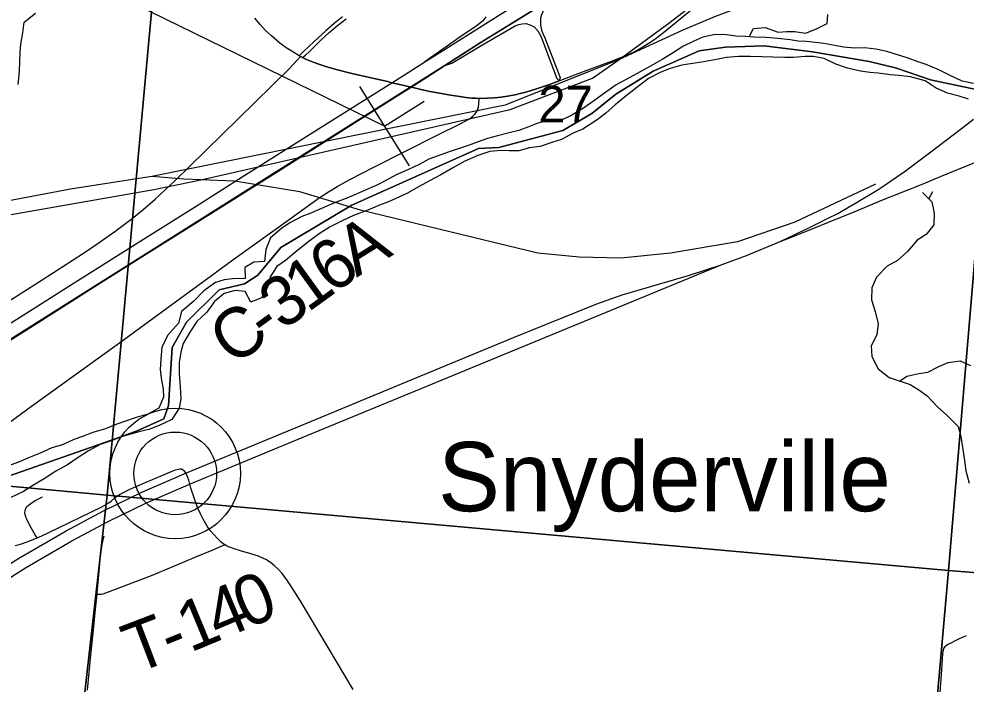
# Model space of a CAD drawing. Extents: x 0 to 1134, y 0 to 440.
# Drawn here: x 395.41 to 427.82, y 180.01 to 202.75 of the extents above; entities that cross this region are included whole.
import ezdxf

# ---------------------------------------------------------------- set-up
doc = ezdxf.new("R2010")
doc.units = 0
for name, color, linetype in [('Default', 7, 'Continuous'), ('GM_X_County_Road', 7, 'Continuous'), ('GM_X_County_Road_Text', 7, 'Continuous'), ('GM_X_Interchange_Ramps', 7, 'Continuous'), ('GM_X_Major_River', 7, 'Continuous'), ('GM_X_Minor_River', 7, 'Continuous'), ('GM_X_Rail_Line', 7, 'Continuous'), ('GM_X_Section', 7, 'Continuous'), ('GM_X_Section_Text', 7, 'Continuous'), ('GM_X_State_Location', 7, 'Continuous'), ('GM_X_State_Route', 7, 'Continuous'), ('GM_X_Township', 7, 'Continuous'), ('GM_X_Township_Road', 7, 'Continuous'), ('GM_X_Township_Road_Text', 7, 'Continuous'), ('GM_X_Unincorporated', 7, 'Continuous'), ('GM_X_Unincorporated_Location', 7, 'Continuous'), ('GM_X_Unincorporated_Text', 7, 'Continuous'), ('SH_Data', 7, 'Continuous'), ('SN_P_Signs', 7, 'Continuous')]:
    doc.layers.add(name, color=color, linetype=linetype)

msp = doc.modelspace()

# ---------------------------------------------------------------- linework, layer by layer
at = {"layer": 'Default'}
for points in [[(428.641, 212.888), (424.922, 210.575), (421.466, 208.395), (417.329, 205.771), (415.897, 204.869), (413.681, 203.473), (412.971, 203.034), (411.196, 201.936), (409.987, 201.156), (408.499, 200.212), (406.885, 199.202), (404.296, 197.561), (401.444, 195.77), (398.739, 194.065), (395.808, 192.216), (393.095, 190.508), (390.63, 188.941), (388.78, 187.783), (386.071, 186.068), (383.39, 184.383), (380.76, 182.721), (378.447, 181.267)], [(375.525, 180.013), (379.132, 182.26), (383.333, 184.928), (384.752, 185.823), (388.22, 188.011), (393.821, 191.534), (395.556, 192.627), (397.21, 193.672), (399.89, 195.36), (401.467, 196.354), (403.042, 197.35), (404.464, 198.24), (407.223, 199.98), (408.168, 200.573), (408.723, 200.921), (409.296, 201.282), (409.905, 201.666), (410.773, 202.212), (414.266, 204.419), (415.098, 204.944)], [(370.709, 176.423), (408.499, 200.212), (408.832, 200.421), (409.33, 200.733), (409.987, 201.156), (370.709, 176.423)]]:
    msp.add_lwpolyline(points, dxfattribs=at)
at = {"layer": 'GM_X_County_Road'}
msp.add_line((405.044, 201.463), (405.113, 201.431), dxfattribs=at)
for points in [[(413.898, 200.641), (414.34, 200.804), (414.817, 200.984), (415.689, 201.31), (416.207, 201.515), (416.457, 201.633), (416.701, 201.764), (416.938, 201.908), (417.168, 202.065), (417.462, 202.292), (418.472, 203.113)], [(394.394, 192.689), (396.204, 193.835), (397.614, 194.743), (398.155, 195.107), (398.686, 195.485), (399.282, 195.932), (399.645, 196.222), (400.064, 196.59), (400.749, 197.222), (401.247, 197.708), (403.477, 199.898), (404.674, 201.073), (405.044, 201.463)], [(405.113, 201.431), (405.246, 201.37), (405.472, 201.275), (405.702, 201.19), (405.948, 201.111), (406.261, 201.022), (406.798, 200.885), (408.018, 200.608), (408.168, 200.573), (408.493, 200.496), (408.832, 200.421), (409.033, 200.376), (409.12, 200.356)], [(409.12, 200.356), (409.471, 200.276), (409.868, 200.197), (410.178, 200.145), (410.493, 200.097), (410.702, 200.069), (410.91, 200.047), (411.034, 200.038), (411.161, 200.034)], [(411.161, 200.034), (411.426, 200.041), (411.678, 200.057), (411.914, 200.079), (412.122, 200.108), (412.386, 200.157), (412.561, 200.198), (412.75, 200.248), (413.121, 200.361), (413.593, 200.526), (413.898, 200.641)], [(393.607, 187.875), (395.714, 189.417), (398.888, 191.709), (400.472, 192.86), (401.828, 193.849), (402.731, 194.51), (404.697, 195.927), (405.685, 196.631), (405.996, 196.838), (406.316, 197.032), (406.726, 197.257), (407.556, 197.681), (409.72, 198.774), (410.555, 199.19), (410.798, 199.324), (410.874, 199.375), (410.945, 199.431), (411.009, 199.493), (411.065, 199.562), (411.105, 199.638), (411.135, 199.738), (411.15, 199.861), (411.161, 200.034)]]:
    msp.add_lwpolyline(points, dxfattribs=at)
at = {"layer": 'GM_X_Interchange_Ramps'}
for points in [[(406.484, 202.821), (406.189, 202.594), (405.905, 202.351), (405.494, 201.972), (405.161, 201.647), (405, 201.489)], [(405.113, 201.431), (405.21, 201.518), (405.349, 201.643), (405.747, 202.037), (406.024, 202.288), (406.31, 202.528), (406.608, 202.752)], [(411.381, 202.827), (411.33, 202.749), (411.269, 202.679), (411.2, 202.616), (411.052, 202.502), (410.5, 202.13), (409.296, 201.282)]]:
    msp.add_lwpolyline(points, dxfattribs=at)
at = {"layer": 'GM_X_Major_River'}
for points in [[(428.071, 200.539), (427.685, 200.628), (427.279, 200.819), (426.884, 201.01), (426.454, 201.191), (426.149, 201.3), (425.843, 201.41), (425.469, 201.52), (425.107, 201.642), (424.732, 201.719), (424.345, 201.762), (424.014, 201.758), (423.627, 201.789), (423.332, 201.841), (422.957, 201.918), (422.365, 201.976), (422.08, 201.994), (421.796, 202.034), (421.375, 202.089), (420.976, 202.121), (420.554, 202.13), (420.258, 202.148), (419.939, 202.166), (419.62, 202.208), (419.233, 202.216), (418.809, 202.134), (418.509, 201.992), (418.128, 201.807), (417.735, 201.564), (417.422, 201.366), (417.098, 201.179), (416.671, 200.949), (416.313, 200.751), (415.851, 200.499), (415.445, 200.211), (415.12, 199.979), (414.726, 199.702), (414.333, 199.46), (413.975, 199.285), (413.576, 199.305), (413.163, 199.189), (412.818, 199.048), (412.519, 198.94), (412.14, 198.846), (411.784, 198.751), (411.44, 198.667), (411.118, 198.549), (410.819, 198.441), (410.508, 198.334), (410.094, 198.195), (409.749, 198.066), (409.439, 197.958), (409.127, 197.783), (408.735, 197.609), (408.32, 197.424), (407.962, 197.226), (407.65, 197.073), (407.235, 196.889), (406.924, 196.747), (406.625, 196.628), (406.21, 196.466), (405.761, 196.27), (405.392, 196.107), (405.093, 196), (404.701, 195.792), (404.4, 195.593), (404.016, 195.271), (403.858, 194.863), (403.815, 194.453), (403.449, 194.439), (403.137, 194.252), (403.151, 193.875), (402.718, 193.861), (402.432, 193.834), (402.133, 193.737), (401.738, 193.449), (401.388, 193.103), (400.97, 192.747), (400.869, 192.35), (400.495, 191.925), (400.292, 191.519), (400.26, 191.131), (400.24, 190.755), (400.289, 190.401), (400.34, 190.103), (400.356, 189.817), (400.188, 189.444), (399.818, 189.236), (399.416, 189.119)], [(427.899, 200.007), (427.582, 200.116), (427.185, 200.216), (426.801, 200.385), (426.419, 200.632), (425.92, 200.769), (425.522, 200.823), (425.226, 200.841), (424.816, 200.896), (424.532, 200.925), (424.202, 200.966), (423.759, 201.067), (423.363, 201.201), (422.968, 201.404), (422.604, 201.469), (422.319, 201.464), (421.919, 201.438), (421.622, 201.434), (421.212, 201.443), (420.836, 201.462), (420.437, 201.471), (420.037, 201.468), (419.626, 201.432), (419.282, 201.371), (418.778, 201.279), (418.389, 201.219), (418.091, 201.169), (417.689, 201.052), (417.378, 200.933), (416.951, 200.714), (416.556, 200.404), (416.127, 200.082), (415.813, 199.815), (415.487, 199.526), (415.197, 199.304), (414.71, 198.984), (414.376, 198.843), (413.972, 198.635), (413.673, 198.539), (413.248, 198.388), (412.881, 198.339), (412.514, 198.245), (412.183, 198.24), (411.898, 198.258), (411.521, 198.221), (411.107, 198.081), (410.646, 197.875), (410.277, 197.677), (409.849, 197.424), (409.456, 197.216), (409.109, 197.018), (408.682, 196.788), (408.059, 196.494), (407.749, 196.387), (407.346, 196.213), (406.851, 196.03), (406.493, 195.855), (406.055, 195.648), (405.685, 195.405), (405.29, 195.117), (404.883, 194.784), (404.523, 194.495), (404.233, 194.285), (404.008, 193.936), (403.921, 193.607), (403.707, 193.212), (403.339, 193.072), (403.153, 193.43), (402.811, 193.471), (402.433, 193.366), (402.095, 193.088), (401.836, 192.728), (401.498, 192.405), (401.25, 192.045), (401.025, 191.651), (400.95, 191.356), (400.885, 191.004), (400.888, 190.627), (400.923, 190.17), (400.948, 189.759), (400.895, 189.44)], [(400.895, 189.44), (400.635, 189.058), (400.209, 188.851), (399.852, 188.71), (399.554, 188.648), (399.267, 188.563), (398.945, 188.468), (398.531, 188.317), (398.186, 188.199), (397.782, 187.98), (397.399, 187.726), (397.064, 187.505), (396.671, 187.285), (396.265, 187.021), (395.942, 186.834), (395.56, 186.591), (395.11, 186.373)], [(399.416, 189.119), (399.048, 189.002), (398.761, 188.894), (398.369, 188.731), (397.933, 188.604), (397.576, 188.475), (397.288, 188.367), (396.896, 188.182), (396.529, 188.087), (396.137, 187.902), (395.734, 187.74), (395.446, 187.62), (395.078, 187.48)]]:
    msp.add_lwpolyline(points, dxfattribs=at)
at = {"layer": 'GM_X_Minor_River'}
for points in [[(395.378, 200.505), (395.429, 200.96), (395.433, 201.313), (395.448, 201.609), (395.475, 201.893), (395.536, 202.28), (395.586, 202.644), (395.978, 202.947)], [(420.399, 202.14), (420.54, 202.428), (420.95, 202.457), (421.393, 202.304), (421.678, 202.323), (421.963, 202.32), (422.327, 202.27), (422.705, 202.414), (423.072, 202.592), (423.087, 202.91)], [(426.328, 196.812), (426.654, 196.501), (426.729, 196.113), (426.713, 195.714), (426.458, 195.375), (426.148, 195.186), (425.813, 194.802), (425.479, 194.487), (425.123, 194.298), (424.754, 193.926), (424.601, 193.552), (424.585, 193.142), (424.705, 192.742), (424.814, 192.331), (424.764, 191.944), (424.577, 191.57), (424.595, 191.206), (424.818, 190.782), (425.19, 190.493), (425.905, 190.245), (426.199, 190.071), (426.493, 189.862), (426.841, 189.482), (427.168, 189.205), (427.551, 188.813), (427.638, 188.47), (427.702, 188.105), (427.765, 187.649), (427.817, 187.295), (427.926, 186.872)], [(426.546, 196.604), (426.682, 196.854)], [(425.548, 190.369), (425.795, 190.531), (426.206, 190.629), (426.514, 190.671), (426.893, 190.871), (427.213, 191.004), (427.624, 191.056), (427.976, 190.904)]]:
    msp.add_lwpolyline(points, dxfattribs=at)
at = {"layer": 'GM_X_Rail_Line'}
for points in [[(415.945, 201.369), (417.65, 202.606), (424.392, 207.798), (441.828, 209.955)], [(440.214, 208.721), (437.468, 207.991), (422.252, 203.963), (419.273, 202.842), (418.129, 202.373), (415.945, 201.369)], [(415.945, 201.369), (412.045, 199.798), (399.953, 197.365)], [(401.626, 197.251), (412.216, 199.658), (415.032, 200.731), (415.945, 201.369)], [(421.456, 195.143), (422.465, 195.622), (423.06, 195.916), (423.428, 196.102), (423.8, 196.316), (424.014, 196.435), (424.834, 196.935), (425.705, 197.525), (426.617, 198.205), (427.659, 199.01), (428.072, 199.33)], [(421.456, 195.143), (421.702, 195.227), (422.47, 195.542), (423.31, 195.886), (423.908, 196.125), (424.938, 196.554), (426.354, 197.112), (426.942, 197.359), (429.163, 198.261)], [(235.537, 142.526), (242.297, 147.201), (254.969, 154.995), (262.517, 161.215), (265.593, 163.533), (269.193, 166.026), (271.762, 167.674), (277.55, 171.187), (282.207, 173.973), (284.647, 175.386), (295.115, 179.81), (306.646, 182.954), (315.223, 183.324), (317.252, 182.945), (319.457, 182.521), (322.574, 182.342), (325.613, 182.903), (328.618, 183.462), (332.907, 184.232), (342.891, 186.315), (382.421, 193.847), (400.022, 196.925), (401.626, 197.251)], [(399.953, 197.365), (397.165, 196.93), (382.347, 194.129), (367.827, 191.319), (354.07, 188.715), (344.21, 186.71), (332.963, 184.495), (329.17, 183.787)], [(401.626, 197.251), (401.053, 197.274), (399.953, 197.365)], [(424.721, 197.101), (421.955, 195.806), (419.993, 195.124), (417.702, 194.739), (416.003, 194.571), (414.583, 194.602), (413.165, 194.739), (410.955, 195.277), (407.094, 196.212), (405.016, 196.836), (402.785, 197.205), (401.626, 197.251)], [(375.894, 171.03), (380.56, 174.234), (384.557, 176.98), (393.276, 182.973), (395.428, 184.322), (397.021, 185.247), (398.298, 185.933), (399.61, 186.564), (401.142, 187.229), (404.951, 188.808), (408.826, 190.405), (412.333, 191.853), (415.182, 193.009), (416.056, 193.314), (416.872, 193.561), (418.36, 193.986), (419.437, 194.344), (420.301, 194.658), (421.456, 195.143)], [(366.276, 163.905), (370.435, 166.769), (372.873, 168.451), (376.123, 170.702), (380.788, 173.905), (384.784, 176.652), (393.497, 182.64), (395.636, 183.98), (397.217, 184.899), (398.481, 185.578), (399.777, 186.201), (401.299, 186.861), (405.104, 188.439), (408.98, 190.036), (412.486, 191.484), (419.437, 194.344)]]:
    msp.add_lwpolyline(points, dxfattribs=at)
at = {"layer": 'GM_X_Section'}
for points in [[(370.553, 219.864), (401.186, 216.549), (398.424, 186.464), (367.659, 189.293)], [(401.186, 216.549), (429.777, 214.186), (427.217, 183.893), (398.424, 186.464)], [(429.777, 214.186), (460.45, 211.914), (458.022, 181.403), (427.217, 183.893)], [(367.659, 189.293), (398.424, 186.464), (395.015, 156.4), (364.647, 159.213)], [(398.424, 186.464), (427.217, 183.893), (424.544, 153.681), (395.015, 156.4)], [(427.217, 183.893), (458.022, 181.403), (454.792, 151.155), (424.544, 153.681)]]:
    msp.add_lwpolyline(points, close=True, dxfattribs=at)
at = {"layer": 'GM_X_State_Route'}
msp.add_line((405.113, 201.431), (405.044, 201.463), dxfattribs=at)
for points in [[(375.525, 180.013), (379.132, 182.26), (383.333, 184.928), (384.752, 185.823), (388.22, 188.011), (393.821, 191.534), (395.556, 192.627), (397.21, 193.672), (399.89, 195.36), (401.467, 196.354), (403.042, 197.35), (404.464, 198.24), (407.223, 199.98), (408.168, 200.573), (408.723, 200.921), (409.296, 201.282), (409.905, 201.666), (410.773, 202.212), (414.266, 204.419), (415.098, 204.944)], [(409.987, 201.156), (411.196, 201.936), (412.971, 203.034), (413.681, 203.473), (415.897, 204.869)], [(415.897, 204.869), (415.724, 204.678), (414.89, 204.106), (413.672, 203.317), (413.491, 203.199), (413.371, 203.075), (413.322, 202.972), (413.293, 202.893), (413.258, 202.775), (413.253, 202.656), (413.253, 202.538), (413.302, 202.34), (413.348, 202.231), (413.4, 202.104), (413.907, 200.807)], [(405.044, 201.463), (405, 201.489), (404.718, 201.657), (404.552, 201.763), (404.33, 201.929), (404.048, 202.17), (403.846, 202.362), (403.658, 202.566), (403.483, 202.783)], [(409.987, 201.156), (410.223, 201.238), (411.189, 201.817), (412.387, 202.52), (412.515, 202.562), (412.623, 202.582), (412.763, 202.591), (412.896, 202.55), (413.041, 202.481), (413.163, 202.351), (413.258, 202.184), (413.289, 202.104), (413.819, 200.715), (413.898, 200.641)], [(409.12, 200.356), (409.033, 200.376), (408.832, 200.421), (408.493, 200.496), (408.168, 200.573), (408.018, 200.608), (406.798, 200.885), (406.261, 201.022), (405.948, 201.111), (405.702, 201.19), (405.472, 201.275), (405.246, 201.37), (405.113, 201.431)], [(408.499, 200.212), (408.832, 200.421), (409.33, 200.733), (409.987, 201.156)], [(413.907, 200.807), (413.929, 200.751), (413.898, 200.641)], [(411.161, 200.034), (411.034, 200.038), (410.91, 200.047), (410.702, 200.069), (410.493, 200.097), (410.178, 200.145), (409.868, 200.197), (409.471, 200.276), (409.12, 200.356)], [(413.898, 200.641), (413.593, 200.526), (413.121, 200.361), (412.75, 200.248), (412.561, 200.198), (412.386, 200.157), (412.122, 200.108), (411.914, 200.079), (411.678, 200.057), (411.426, 200.041), (411.161, 200.034)], [(370.709, 176.423), (371.022, 176.622), (373.561, 178.219), (375.846, 179.652), (378.447, 181.267), (380.76, 182.721), (383.39, 184.383), (386.071, 186.068), (388.78, 187.783), (390.63, 188.941), (393.095, 190.508), (395.808, 192.216), (398.739, 194.065), (401.444, 195.77), (404.296, 197.561), (406.885, 199.202), (408.499, 200.212)]]:
    msp.add_lwpolyline(points, dxfattribs=at)
at = {"layer": 'GM_X_Township'}
for points in [[(395.019, 187.105), (398.569, 188.347), (399.453, 188.665), (400.361, 189.078), (400.526, 189.532), (400.65, 191.512), (401.145, 192.378), (402.259, 193.492), (403.126, 193.699), (403.58, 193.988), (404.364, 194.937), (406.798, 196.381), (411.131, 198.32), (411.832, 198.361), (414.02, 198.939), (415.01, 199.517), (415.836, 200.177), (417.114, 200.961), (418.682, 201.663), (419.591, 201.787), (420.911, 201.828), (422.562, 201.622), (424.502, 201.292), (425.41, 201.086), (426.606, 200.673), (428.546, 200.26)], [(428.546, 200.26), (426.606, 200.673), (425.41, 201.086), (424.502, 201.292), (422.562, 201.622), (420.911, 201.828), (419.591, 201.787), (418.682, 201.663), (417.114, 200.961), (415.836, 200.177), (415.01, 199.517), (414.02, 198.939), (411.832, 198.361), (411.131, 198.32), (406.798, 196.381), (404.364, 194.937), (403.58, 193.988), (403.126, 193.699), (402.259, 193.492), (401.145, 192.378), (400.65, 191.512), (400.526, 189.532), (400.361, 189.078), (399.453, 188.665), (398.569, 188.347), (395.019, 187.105)]]:
    msp.add_lwpolyline(points, dxfattribs=at)
at = {"layer": 'GM_X_Township_Road'}
for points in [[(396.026, 185.002), (396.067, 185.019), (396.401, 185.174), (398.24, 186.062), (398.402, 186.156), (398.485, 186.208), (398.561, 186.259), (398.698, 186.383), (398.85, 186.483), (399.01, 186.574), (399.175, 186.656), (399.685, 186.881), (400.649, 187.288), (400.759, 187.33), (400.867, 187.355), (400.912, 187.362), (400.946, 187.362), (400.975, 187.353)], [(402.45, 184.77), (402.396, 184.807), (402.32, 184.871), (402.201, 184.983), (402.073, 185.119), (401.955, 185.261), (401.848, 185.41), (401.707, 185.649), (401.664, 185.732), (401.622, 185.822), (401.581, 185.906), (401.544, 185.991), (401.506, 186.078), (401.29, 186.708), (401.216, 186.977), (401.188, 187.065), (401.155, 187.15), (401.114, 187.228), (401.062, 187.298), (401.029, 187.323), (400.975, 187.353)], [(396.026, 185.002), (395.966, 185.107), (395.78, 185.432), (395.675, 185.645), (395.655, 185.692), (395.637, 185.736), (395.621, 185.8), (395.612, 185.856), (395.617, 185.932), (395.629, 185.982), (395.648, 186.028), (395.672, 186.063), (395.716, 186.11), (395.813, 186.185), (395.962, 186.28), (396.208, 186.412)], [(395.277, 184.74), (395.458, 184.788), (395.723, 184.879), (396.026, 185.002)], [(398.083, 183.081), (398.088, 183.124), (398.151, 183.866), (398.188, 184.253), (398.215, 184.537), (398.238, 184.688), (398.251, 184.788), (398.285, 184.928), (398.323, 185.066)], [(398.083, 183.081), (398.141, 183.081), (398.215, 183.081), (398.291, 183.089), (398.807, 183.28), (399.937, 183.718), (400.703, 184.037), (401.459, 184.356), (402.022, 184.59), (402.388, 184.744), (402.45, 184.77)], [(406.839, 179.815), (406.563, 180.302), (405.988, 181.261), (405.025, 182.86), (404.734, 183.336), (404.58, 183.565), (404.413, 183.785), (404.29, 183.921), (404.154, 184.044), (404.01, 184.16), (403.857, 184.261), (403.777, 184.305), (403.608, 184.377), (403.344, 184.462), (402.993, 184.565), (402.773, 184.634), (402.663, 184.671), (402.6, 184.692), (402.529, 184.721), (402.473, 184.754), (402.45, 184.77)], [(397.749, 179.799), (397.869, 181.004), (397.947, 181.744), (398.029, 182.571), (398.083, 183.081)], [(426.928, 179.557), (426.956, 180.025), (426.989, 180.493), (427.026, 181.038), (427.034, 181.113), (427.063, 181.223), (427.104, 181.291), (427.143, 181.33), (427.19, 181.358), (427.308, 181.421), (427.436, 181.489), (427.592, 181.564), (427.729, 181.625), (427.84, 181.669)]]:
    msp.add_lwpolyline(points, dxfattribs=at)
at = {"layer": 'GM_X_Unincorporated'}
for radius in [2.232, 1.415]:
    msp.add_circle((400.754, 187.21), radius, dxfattribs=at)
at = {"layer": 'GM_X_Unincorporated_Location'}
msp.add_line((400.754, 187.21), (400.754, 187.21), dxfattribs=at)
at = {"layer": 'SH_Data'}
msp.add_line((407.915, 199.086), (388.032, 208.812), dxfattribs=at)
at = {"layer": 'SN_P_Signs'}
for p, q in [((407.065, 200.442), (408.764, 197.73)), ((407.915, 199.086), (409.271, 199.936))]:
    msp.add_line(p, q, dxfattribs=at)

# ---------------------------------------------------------------- texts
at = {"layer": 'GM_X_County_Road_Text'}
for s, rotation, p in [('A', 31.71, (406.962, 193.902)), ('6', 35.7385, (406.136, 193.306)), ('1', 35.8426, (405.285, 192.692)), ('3', 35.8707, (404.435, 192.077)), ('C', 35.8816, (402.733, 190.846)), ('-', 35.8855, (403.868, 191.667))]:
    msp.add_text(s, height=1.705, rotation=rotation, dxfattribs=at).set_placement(p)
at = {"layer": 'GM_X_Section_Text'}
msp.add_text('27', height=1.2557, rotation=0, dxfattribs=at).set_placement((413.182, 199.211))
at = {"layer": 'GM_X_State_Location'}
for s in ['s', 'r']:
    msp.add_text(s, height=0.00568, dxfattribs=at).set_placement((407.862, 199.156))
at = {"layer": 'GM_X_Township_Road_Text'}
for s, rotation, p in [('0', 22.7539, (403.195, 181.878)), ('4', 22.7482, (402.234, 181.475)), ('1', 22.5123, (401.265, 181.073)), ('T', 20.9128, (399.383, 180.343)), ('-', 21.7639, (400.598, 180.807))]:
    msp.add_text(s, height=1.705, rotation=rotation, dxfattribs=at).set_placement(p)
at = {"layer": 'GM_X_Unincorporated_Text'}
msp.add_text('Snyderville', height=2.36932, rotation=0, dxfattribs=at).set_placement((409.751, 185.916))

doc.saveas('drawing.dxf')
